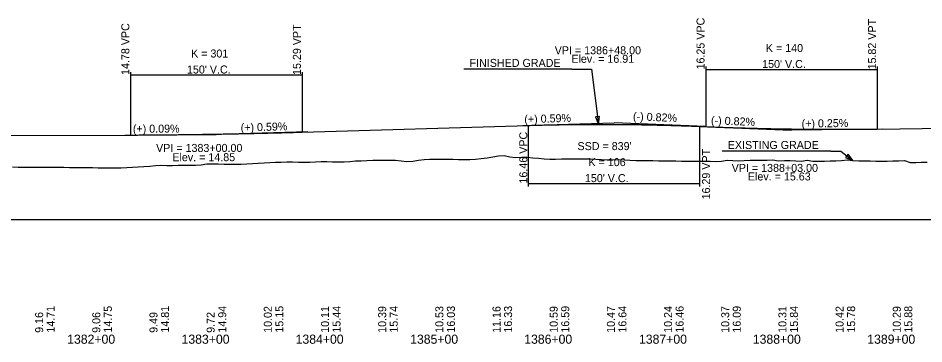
# Model space of a CAD drawing. Extents: x 2360994 to 2383826, y 330623 to 403123.
# Drawn here: x 2369652 to 2370444, y 351764 to 352049 of the extents above; entities that cross this region are included whole.
import ezdxf

# ---------------------------------------------------------------- set-up
doc = ezdxf.new("R2010")
doc.units = 0
for name, color, linetype in [('RD_DDB_GradeTX', 7, 'Continuous'), ('RD_DDB_Profile_EX', 7, 'Continuous'), ('RD_DDB_Profile_Lbl', 7, 'Continuous'), ('RD_DDB_Profile_PR', 7, 'Continuous'), ('RD_DDB_StaTX', 7, 'Continuous'), ('RD_DDB_StripGrade', 7, 'Continuous'), ('RD_DDB_VCLbl', 7, 'Continuous'), ('RD_GPK_Profile_Cell', 7, 'Continuous'), ('RD_TX_Profile', 7, 'Continuous')]:
    doc.layers.add(name, color=color, linetype=linetype)

msp = doc.modelspace()

# ---------------------------------------------------------------- linework, layer by layer
at = {"layer": 'RD_DDB_GradeTX'}
for p, q in [((2370093.6, 351955.05), (2370173.57, 351957.42)), ((2370253.5, 351954.14), (2370173.57, 351957.42)), ((2370248.63, 351954.34), (2370328.57, 351951.06)), ((2370408.56, 351952.05), (2370328.57, 351951.06)), ((2369745.57, 351946.75), (2369825.57, 351947.12)), ((2369905.53, 351949.49), (2369825.57, 351947.12))]:
    msp.add_line(p, q, dxfattribs=at)
at = {"layer": 'RD_DDB_Profile_EX'}
for points in [[(2369917.36, 351923.69), (2369922.36, 351923.6), (2369927.36, 351923.34), (2369932.36, 351923.39), (2369937.36, 351923.44), (2369942.36, 351923.6), (2369947.36, 351924.09), (2369952.36, 351924.29), (2369957.36, 351924.5), (2369962.36, 351924.68), (2369967.36, 351924.75), (2369972.36, 351924.81), (2369977.36, 351924.87), (2369982.36, 351924.91), (2369987.36, 351924.31), (2369992.36, 351923.71), (2369997.36, 351924.01), (2370002.36, 351924.72), (2370007.36, 351925.43), (2370012.36, 351925.66), (2370017.36, 351925.59), (2370022.36, 351925.56), (2370027.36, 351925.54), (2370032.36, 351925.52), (2370037.36, 351925.49), (2370042.36, 351925.47), (2370047.36, 351925.41), (2370052.36, 351925.53), (2370057.36, 351926.17), (2370062.36, 351926.81), (2370067.36, 351927.58), (2370072.36, 351928.5), (2370077.36, 351928.77), (2370082.36, 351927.62), (2370087.36, 351927.19), (2370092.36, 351927.29), (2370097.36, 351927.27), (2370102.36, 351926.95), (2370107.36, 351926.48), (2370112.36, 351925.88), (2370117.36, 351925.56), (2370122.36, 351925.72), (2370127.36, 351925.88), (2370132.36, 351925.9), (2370137.36, 351925.99), (2370142.36, 351926.06), (2370147.36, 351926.06), (2370152.36, 351925.87), (2370157.36, 351925.64), (2370162.36, 351925.42), (2370167.36, 351925.19), (2370172.36, 351925.02), (2370177.36, 351925.35), (2370182.36, 351925.09), (2370187.36, 351924.83), (2370192.36, 351924.63), (2370197.36, 351924.64), (2370202.36, 351924.64), (2370207.36, 351924.48), (2370212.36, 351924.32), (2370217.36, 351924.15), (2370222.36, 351924.07), (2370227.36, 351924.07), (2370232.36, 351924.06), (2370237.36, 351924.02), (2370242.36, 351923.98), (2370247.36, 351923.91), (2370252.36, 351923.9), (2370257.36, 351923.85), (2370262.36, 351923.72), (2370267.36, 351923.93), (2370272.36, 351924.85), (2370277.36, 351924.63), (2370282.36, 351924.19), (2370287.36, 351924.45), (2370292.36, 351924.71), (2370297.36, 351924.76), (2370302.36, 351924.83), (2370307.36, 351924.9), (2370312.36, 351924.97), (2370317.36, 351924.2), (2370322.36, 351924.45), (2370327.36, 351924.41), (2370332.36, 351924.1), (2370337.36, 351924.05), (2370342.36, 351924.75), (2370347.36, 351924.03), (2370352.36, 351924.02), (2370357.36, 351924.06), (2370362.36, 351924.09), (2370367.36, 351924.13), (2370372.36, 351924.57), (2370377.36, 351925.18), (2370382.36, 351924.57), (2370387.36, 351924.24), (2370392.36, 351924.2), (2370397.36, 351924.22), (2370402.36, 351924.01), (2370407.36, 351923.82), (2370412.36, 351923.97), (2370417.36, 351924.11)], [(2369647.36, 351918.97), (2369652.36, 351918.81), (2369657.36, 351918.65), (2369662.36, 351918.54), (2369667.36, 351918.59), (2369672.36, 351918.64), (2369677.36, 351918.69), (2369682.36, 351918.75), (2369687.36, 351918.67), (2369692.36, 351918.6), (2369697.36, 351918.52), (2369702.36, 351918.45), (2369707.36, 351918.39), (2369712.36, 351918.33), (2369717.36, 351918.27), (2369722.36, 351918.22), (2369727.36, 351918.16), (2369732.36, 351918.12), (2369737.36, 351918.16), (2369742.36, 351918.2), (2369747.36, 351918.41), (2369752.36, 351918.72), (2369757.36, 351919.04), (2369762.36, 351919.36), (2369767.36, 351919.68), (2369772.36, 351920.01), (2369777.36, 351920.49), (2369782.36, 351920.24), (2369787.36, 351920.21), (2369792.36, 351920.28), (2369797.36, 351920.36), (2369802.36, 351920.43), (2369807.36, 351920.51), (2369812.36, 351920.59), (2369817.36, 351921.46), (2369822.36, 351921.55), (2369827.36, 351921.47), (2369832.36, 351921.39), (2369837.36, 351921.3), (2369842.36, 351921.25), (2369847.36, 351921.28), (2369852.36, 351921.44), (2369857.36, 351921.78), (2369862.36, 351922.13), (2369867.36, 351922.48), (2369872.36, 351922.88), (2369877.36, 351923.03), (2369882.36, 351923.17), (2369887.36, 351923.32), (2369892.36, 351923.47), (2369897.36, 351923.15), (2369902.36, 351922.97), (2369907.36, 351923.12), (2369912.36, 351923.27), (2369917.36, 351923.69)], [(2370417.36, 351924.11), (2370422.36, 351924.26), (2370427.36, 351924.4), (2370432.36, 351922.73), (2370437.36, 351922.81), (2370442.36, 351922.91), (2370447.36, 351923.07)]]:
    msp.add_lwpolyline(points, dxfattribs=at)
at = {"layer": 'RD_DDB_Profile_PR'}
for p, q in [((2369900.57, 351949.34), (2370098.57, 351955.2)), ((2370248.57, 351954.34), (2370253.57, 351954.13)), ((2370403.57, 351951.98), (2370510.57, 351953.31)), ((2369592.72, 351946.03), (2369750.57, 351946.77))]:
    msp.add_line(p, q, dxfattribs=at)
for points in [[(2370098.57, 351955.2), (2370101.57, 351955.28), (2370104.57, 351955.37), (2370107.57, 351955.45), (2370110.57, 351955.52), (2370113.57, 351955.59), (2370116.57, 351955.65), (2370119.57, 351955.72), (2370122.57, 351955.77), (2370125.57, 351955.83), (2370128.57, 351955.87), (2370131.57, 351955.92), (2370134.57, 351955.96), (2370137.57, 351955.99), (2370140.57, 351956.03), (2370143.57, 351956.05), (2370146.57, 351956.08), (2370149.57, 351956.09), (2370152.57, 351956.11), (2370155.57, 351956.12), (2370158.57, 351956.13), (2370161.57, 351956.13), (2370164.57, 351956.12), (2370167.57, 351956.12), (2370170.57, 351956.11), (2370173.57, 351956.09), (2370176.57, 351956.07), (2370179.57, 351956.05), (2370182.57, 351956.02), (2370185.57, 351955.99), (2370188.57, 351955.95), (2370191.57, 351955.91), (2370194.57, 351955.87), (2370197.57, 351955.82), (2370200.57, 351955.77), (2370203.57, 351955.71), (2370206.57, 351955.65), (2370209.57, 351955.58), (2370212.57, 351955.51), (2370215.57, 351955.44), (2370218.57, 351955.36), (2370221.57, 351955.28), (2370224.57, 351955.19), (2370227.57, 351955.1), (2370230.57, 351955), (2370233.57, 351954.9), (2370236.57, 351954.8), (2370239.57, 351954.69), (2370242.57, 351954.58), (2370245.57, 351954.46), (2370248.57, 351954.34)], [(2370253.57, 351954.13), (2370256.57, 351954.01), (2370259.57, 351953.89), (2370262.57, 351953.78), (2370265.57, 351953.67), (2370268.57, 351953.56), (2370271.57, 351953.45), (2370274.57, 351953.35), (2370277.57, 351953.25), (2370280.57, 351953.15), (2370283.57, 351953.06), (2370286.57, 351952.97), (2370289.57, 351952.89), (2370292.57, 351952.8), (2370295.57, 351952.72), (2370298.57, 351952.65), (2370301.57, 351952.57), (2370304.57, 351952.5), (2370307.57, 351952.44), (2370310.57, 351952.37), (2370313.57, 351952.31), (2370316.57, 351952.25), (2370319.57, 351952.2), (2370322.57, 351952.15), (2370325.57, 351952.1), (2370328.57, 351952.06), (2370331.57, 351952.02), (2370334.57, 351951.98), (2370337.57, 351951.94), (2370340.57, 351951.91), (2370343.57, 351951.88), (2370346.57, 351951.86), (2370349.57, 351951.83), (2370352.57, 351951.82), (2370355.57, 351951.8), (2370358.57, 351951.79), (2370361.57, 351951.78), (2370364.57, 351951.77), (2370367.57, 351951.77), (2370370.57, 351951.77), (2370373.57, 351951.77), (2370376.57, 351951.78), (2370379.57, 351951.79), (2370382.57, 351951.8), (2370385.57, 351951.82), (2370388.57, 351951.84), (2370391.57, 351951.86), (2370394.57, 351951.89), (2370397.57, 351951.92), (2370400.57, 351951.95), (2370403.57, 351951.98)], [(2369750.57, 351946.77), (2369753.57, 351946.78), (2369756.57, 351946.8), (2369759.57, 351946.82), (2369762.57, 351946.84), (2369765.57, 351946.86), (2369768.57, 351946.88), (2369771.57, 351946.9), (2369774.57, 351946.93), (2369777.57, 351946.96), (2369780.57, 351946.98), (2369783.57, 351947.01), (2369786.57, 351947.05), (2369789.57, 351947.08), (2369792.57, 351947.11), (2369795.57, 351947.15), (2369798.57, 351947.19), (2369801.57, 351947.22), (2369804.57, 351947.26), (2369807.57, 351947.31), (2369810.57, 351947.35), (2369813.57, 351947.39), (2369816.57, 351947.44), (2369819.57, 351947.49), (2369822.57, 351947.54), (2369825.57, 351947.59), (2369828.57, 351947.64), (2369831.57, 351947.69), (2369834.57, 351947.75), (2369837.57, 351947.81), (2369840.57, 351947.86), (2369843.57, 351947.92), (2369846.57, 351947.98), (2369849.57, 351948.05), (2369852.57, 351948.11), (2369855.57, 351948.18), (2369858.57, 351948.24), (2369861.57, 351948.31), (2369864.57, 351948.38), (2369867.57, 351948.45), (2369870.57, 351948.53), (2369873.57, 351948.6), (2369876.57, 351948.68), (2369879.57, 351948.76), (2369882.57, 351948.83), (2369885.57, 351948.92), (2369888.57, 351949), (2369891.57, 351949.08), (2369894.57, 351949.17), (2369897.57, 351949.25), (2369900.57, 351949.34)]]:
    msp.add_spline(points, degree=3, dxfattribs=at)
at = {"layer": 'RD_DDB_VCLbl'}
for p, q in [((2369750.57, 352001.84), (2369750.57, 351946.77)), ((2369750.57, 351999.34), (2369900.57, 351999.34)), ((2369900.57, 352001.84), (2369900.57, 351949.34)), ((2370253.57, 352006.63), (2370253.57, 351954.13)), ((2370253.57, 352004.13), (2370403.57, 352004.13)), ((2370403.57, 352006.63), (2370403.57, 351951.98)), ((2370098.57, 351901.84), (2370098.57, 351955.2)), ((2370248.57, 351901.84), (2370248.57, 351954.34)), ((2370098.57, 351904.34), (2370248.57, 351904.34))]:
    msp.add_line(p, q, dxfattribs=at)
at = {"layer": 'RD_GPK_Profile_Cell'}
msp.add_line((2368825.57, 351872.88), (2374525.57, 351872.88), dxfattribs=at)
at = {"layer": 'RD_TX_Profile'}
for p, q in [((2370136.65, 352004.36), (2370042.08, 352004.36)), ((2370363, 351932.59), (2370267.88, 351932.59))]:
    msp.add_line(p, q, dxfattribs=at)
for points in [[(2370136.65, 352004.36), (2370153.63, 352004.36), (2370159.91, 351956.12)], [(2370363, 351932.59), (2370371.72, 351932.59), (2370382.36, 351924.57)]]:
    msp.add_lwpolyline(points, dxfattribs=at)
for points in [[(2370157.24, 351962.6), (2370159.91, 351956.12), (2370160.84, 351963.06)], [(2370375.87, 351927.2), (2370382.36, 351924.57), (2370378.05, 351930.09)]]:
    msp.add_lwpolyline(points, close=True, dxfattribs=at)

# ---------------------------------------------------------------- texts
at = {"layer": 'RD_DDB_GradeTX'}
for s, rotation, p in [('(+) 0.59%', 1.69455, (2370095.05, 351957.09)), ('(-) 0.82%', 357.64975, (2370189.9, 351959.74)), ('(-) 0.82%', 357.64975, (2370258.11, 351956.25)), ('(+) 0.25%', 0.71018, (2370337.47, 351953.32)), ('(+) 0.09%', 0.26914, (2369752.65, 351948.75)), ('(+) 0.59%', 1.69455, (2369847, 351949.76))]:
    msp.add_text(s, height=7, rotation=rotation, dxfattribs=at).set_placement(p)
at = {"layer": 'RD_DDB_Profile_Lbl'}
for s, p in [('VPI = 1386+48.00', (2370121.55, 352017.42)), ('Elev. = 16.91', (2370136.12, 352009.94)), ('VPI = 1383+00.00', (2369772.96, 351931.99)), ('Elev. = 14.85', (2369787.18, 351923.91)), ('VPI = 1388+03.00', (2370276.31, 351914.52)), ('Elev. = 15.63', (2370290.47, 351907.05))]:
    msp.add_text(s, height=7, dxfattribs=at).set_placement(p)
at = {"layer": 'RD_DDB_StaTX'}
for s, p in [('1382+00', (2369695.2, 351764.2)), ('1383+00', (2369795.23, 351764.2)), ('1384+00', (2369894.99, 351764.2)), ('1385+00', (2369995.13, 351764.2)), ('1386+00', (2370094.9, 351764.2)), ('1387+00', (2370195.25, 351764.2)), ('1388+00', (2370294.79, 351764.2)), ('1389+00', (2370394.89, 351764.2))]:
    msp.add_text(s, height=8, dxfattribs=at).set_placement(p)
at = {"layer": 'RD_DDB_StripGrade'}
for s, p in [('16.25 VPC', (2370252.57, 352004.13)), ('15.82 VPT', (2370402.57, 352004.13)), ('14.78 VPC', (2369749.57, 351999.34)), ('15.29 VPT', (2369899.57, 351999.34)), ('16.46 VPC', (2370097.57, 351904.34)), ('16.29 VPT', (2370257.42, 351890.44)), ('14.71', (2369684.25, 351773.93)), ('14.75', (2369734.25, 351773.93)), ('14.81', (2369784.25, 351773.93)), ('14.94', (2369834.25, 351773.93)), ('10.02', (2369874.16, 351773.74)), ('15.15', (2369884.25, 351773.93)), ('10.11', (2369924.16, 351773.74)), ('15.44', (2369934.25, 351773.93)), ('10.39', (2369974.16, 351773.74)), ('15.74', (2369984.25, 351773.93)), ('10.53', (2370024.16, 351773.74)), ('16.03', (2370034.25, 351773.93)), ('11.16', (2370074.16, 351773.74)), ('16.33', (2370084.25, 351773.93)), ('10.59', (2370124.16, 351773.74)), ('16.59', (2370134.25, 351773.93)), ('10.47', (2370174.16, 351773.74)), ('16.64', (2370184.25, 351773.93)), ('10.24', (2370224.16, 351773.74)), ('16.46', (2370234.25, 351773.93)), ('10.37', (2370274.16, 351773.74)), ('16.09', (2370284.25, 351773.93)), ('10.31', (2370324.16, 351773.74)), ('15.84', (2370334.25, 351773.93)), ('10.42', (2370374.16, 351773.74)), ('15.78', (2370384.25, 351773.93)), ('10.29', (2370424.16, 351773.74)), ('15.88', (2370434.25, 351773.93)), ('9.16', (2369674.16, 351773.74)), ('9.06', (2369724.16, 351773.74)), ('9.49', (2369774.16, 351773.74)), ('9.72', (2369824.16, 351773.74))]:
    msp.add_text(s, height=7, rotation=90, dxfattribs=at).set_placement(p)
at = {"layer": 'RD_DDB_VCLbl'}
for s, p in [('K = 140', (2370306.2, 352019.38)), ('K = 301', (2369803.55, 352014.59)), ("150' V.C.", (2369799.94, 352000.59)), ("150' V.C.", (2370302.94, 352005.38)), ("SSD = 839'", (2370141.47, 351933.59)), ('K = 106', (2370151.06, 351919.59)), ("150' V.C.", (2370147.94, 351905.59))]:
    msp.add_text(s, height=7, dxfattribs=at).set_placement(p)
at = {"layer": 'RD_TX_Profile'}
for s, p in [('FINISHED GRADE', (2370047.08, 352006.36)), ('EXISTING GRADE', (2370272.88, 351934.59))]:
    msp.add_text(s, height=7, dxfattribs=at).set_placement(p)

doc.saveas('drawing.dxf')
